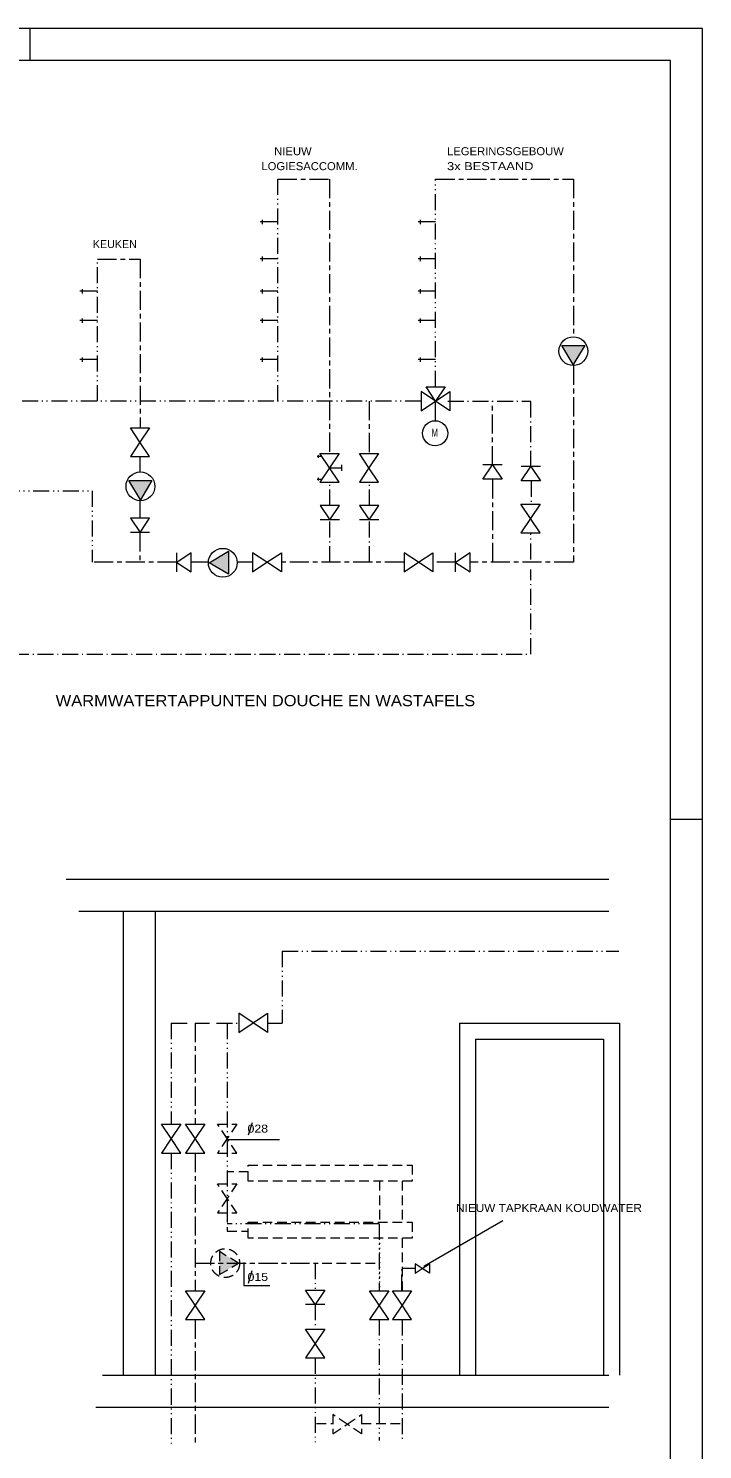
# Model space of a CAD drawing. Extents: x 295824 to 414724, y 24924 to 109024.
# Drawn here: x 393674 to 414724, y 64629 to 109024 of the extents above; entities that cross this region are included whole.
import ezdxf

# ---------------------------------------------------------------- set-up
doc = ezdxf.new("R2010")
doc.units = 0
doc.header["$LTSCALE"] = 100
for name, pattern in [('DASH_DOUBLE_DOT', [9.2, 5, -1.2, 0.3, -1.2, 0.3, -1.2]), ('DOT_DASHED', [7.7, 5, -1.2, 0.3, -1.2]), ('DOTTED', [1.5, 0.3, -1.2]), ('LONG_DASH_SHORT_DASH', [9.9, 6, -1.2, 1.5, -1.2]), ('MEDIUM_DASHED', [4.5, 3, -1.5])]:
    doc.linetypes.add(name, pattern=pattern)
for name, color, linetype, lineweight in [('1', 7, 'Continuous', 13), ('16', 7, 'Continuous', 13), ('30', 7, 'Continuous', 13)]:
    doc.layers.add(name, color=color, linetype=linetype, lineweight=lineweight)

msp = doc.modelspace()

# ---------------------------------------------------------------- hatches: boundary and pattern name
at = {"layer": '30'}
for points in [[(410326.8, 99122.5), (411046.8, 99122.5), (410686.8, 98522.5), (410686.8, 98522.5)], [(396810.4, 94898.8), (397530.4, 94898.8), (397170.4, 94298.8), (397170.4, 94298.8)], [(399922, 92692.6), (399922, 91972.6), (399322, 92332.6), (399322, 92332.6)], [(399637.9, 70813.8), (399637.9, 70093.8), (400237.9, 70453.8), (400237.9, 70453.8)]]:
    msp.add_hatch(color=256, dxfattribs=at).paths.add_polyline_path(points)

# ---------------------------------------------------------------- linework, layer by layer
at = {"layer": '1'}
for p, q in [((393723.6, 108023.8), (393723.6, 109023.8)), ((414723.6, 24923.8), (414723.6, 109023.8)), ((413723.6, 84323.8), (414723.6, 84323.8)), ((406017.2, 70354.9), (408491.4, 71783.4))]:
    msp.add_line(p, q, dxfattribs=at)
for points in [[(414723.6, 109023.8), (304995.6, 109023.8), (295823.6, 109023.8)], [(304995.6, 25923.8), (413723.6, 25923.8), (413723.6, 108023.8), (304995.6, 108023.8)]]:
    msp.add_lwpolyline(points, dxfattribs=at)
at = {"layer": '30', "linetype": 'DASH_DOUBLE_DOT'}
for p, q in [((401457.7, 97381.8), (401457.7, 104318.7)), ((406388, 97830.3), (406388, 104318.7)), ((395827.9, 97381.8), (395827.9, 101820.6)), ((405933, 97381.8), (391003.1, 97381.8)), ((391984.8, 94576.2), (395663, 94576.2)), ((395663, 94576.2), (395663, 92348.1)), ((401594.7, 80202), (412106, 80202)), ((401594.7, 80202), (401594.7, 77952)), ((398130.5, 77952), (398629.9, 77952)), ((398130.5, 77952), (398130.5, 74792)), ((398880.5, 77952), (399329.5, 77952)), ((399542.9, 77952), (400238.9, 77952)), ((399880.5, 77952), (399880.5, 71679.2)), ((401138.9, 77952), (401594.7, 77952)), ((398130.5, 73892), (398130.5, 64823.2)), ((404630.5, 71679.2), (399880.5, 71679.2)), ((404630.5, 71679.2), (404630.5, 69592.1)), ((402630.5, 70452), (402630.5, 69596.3)), ((402630.5, 69167), (402630.5, 68392.2)), ((404630.5, 68692.1), (404630.5, 64909)), ((402630.5, 67492.2), (402630.5, 64859.3))]:
    msp.add_line(p, q, dxfattribs=at)
at = {"layer": '30'}
for p, q in [((400977, 103044.6), (400977, 102905.8)), ((405907.2, 103044.6), (405907.2, 102905.8)), ((401457.7, 102977.9), (400910.4, 102977.9)), ((406388, 102977.9), (405840.6, 102977.9)), ((401457.7, 101827.9), (400910.4, 101827.9)), ((400977, 101894.6), (400977, 101755.8)), ((406388, 101827.9), (405840.6, 101827.9)), ((405907.2, 101894.6), (405907.2, 101755.8)), ((395827.9, 100811.3), (395280.5, 100811.3)), ((395347.2, 100877.9), (395347.2, 100739.2)), ((401457.7, 100811.3), (400910.4, 100811.3)), ((400977, 100877.9), (400977, 100739.2)), ((406388, 100811.3), (405840.6, 100811.3)), ((405907.2, 100877.9), (405907.2, 100739.2)), ((395827.9, 99894.6), (395280.5, 99894.6)), ((395347.2, 99961.3), (395347.2, 99822.5)), ((401457.7, 99894.6), (400910.4, 99894.6)), ((400977, 99961.3), (400977, 99822.5)), ((406388, 99894.6), (405840.6, 99894.6)), ((405907.2, 99961.3), (405907.2, 99822.5)), ((410686.8, 98522.5), (410326.8, 99122.5)), ((410326.8, 99122.5), (411046.8, 99122.5)), ((411046.8, 99122.5), (410686.8, 98522.5)), ((395827.9, 98678), (395280.5, 98678)), ((395347.2, 98744.6), (395347.2, 98605.9)), ((401457.7, 98678), (400910.4, 98678)), ((400977, 98744.6), (400977, 98605.9)), ((406388, 98678), (405840.6, 98678)), ((405907.2, 98744.6), (405907.2, 98605.9)), ((406376.9, 97387.4), (406376.9, 96754.1)), ((402832.6, 95652.3), (402685.6, 95652.3)), ((402718.9, 95693.9), (402718.9, 95610.6)), ((403068.7, 95293.9), (403451.8, 95293.9)), ((403451.8, 95393.9), (403451.8, 95202.3)), ((408464, 95388.2), (407864, 95388.2)), ((409663.2, 95338.2), (409063.2, 95338.2)), ((397170.4, 94298.8), (396810.4, 94898.8)), ((396810.4, 94898.8), (397530.4, 94898.8)), ((397530.4, 94898.8), (397170.4, 94298.8)), ((402834.7, 94935.6), (402685.6, 94935.6)), ((402718.9, 94985.6), (402718.9, 94902.3)), ((397458.6, 93279.7), (396858.6, 93279.7)), ((403383.8, 93670.1), (402783.8, 93670.1)), ((404616.4, 93670.1), (404016.4, 93670.1)), ((398302.9, 92044.4), (398302.9, 92644.4)), ((399322, 92332.6), (399922, 92692.6)), ((399922, 92692.6), (399922, 91972.6)), ((407014.1, 92044.4), (407014.1, 92644.4)), ((399922, 91972.6), (399322, 92332.6)), ((394850.1, 82452), (411793.9, 82452)), ((395249.9, 81452), (411793.9, 81452)), ((396630.5, 81452), (396630.5, 66952)), ((397630.5, 81452), (397630.5, 66952)), ((407130.5, 77952), (407130.5, 66952)), ((407130.5, 77952), (412130.5, 77952)), ((412130.5, 77952), (412130.5, 66952)), ((407630.5, 77452), (407630.5, 66952)), ((400663.2, 74837.5), (400529.9, 74454.2)), ((399913.6, 74312.5), (401512.7, 74312.5)), ((400646.5, 70212.6), (400539.8, 69814.4)), ((402325.1, 69175.5), (402925.1, 69175.5)), ((395982.7, 66952), (411793.9, 66952)), ((395782.9, 65952), (411793.9, 65952))]:
    msp.add_line(p, q, dxfattribs=at)
at = {"layer": '30', "linetype": 'LONG_DASH_SHORT_DASH'}
for p, q in [((410688.9, 98493.8), (410688.9, 92348.1)), ((404311.5, 97381.8), (404311.5, 95745.6)), ((408165.5, 95377.5), (408165.5, 97377.6)), ((397154.9, 95654), (397154.9, 95168.4)), ((408167.4, 94938.2), (408167.4, 92348.1)), ((397154.9, 94269.1), (397154.9, 93729.7)), ((397154.9, 93279.7), (397154.9, 92348.1)), ((398302.9, 92348.1), (395663, 92348.1)), ((399292.3, 92348.1), (398752.9, 92348.1)), ((400677.2, 92348.1), (400191.6, 92348.1)), ((405402.5, 92348.1), (401572.1, 92348.1)), ((407027.2, 92348.1), (406302.5, 92348.1)), ((410688.9, 92348.1), (407477.2, 92348.1)), ((398880.5, 77952), (398880.5, 74792)), ((398880.5, 73892), (398880.5, 69592.1)), ((398880.5, 70452), (402779.2, 70452)), ((398880.5, 68692.1), (398880.5, 64843.2))]:
    msp.add_line(p, q, dxfattribs=at)
at = {"layer": '30', "linetype": 'DOT_DASHED'}
for p, q in [((406766.1, 97377.6), (409364.8, 97377.6)), ((409364.8, 95327.5), (409364.8, 97377.6)), ((403087.2, 94120.1), (403087.2, 94840.8)), ((404319.8, 94120.1), (404319.8, 94840.8)), ((409366.7, 94888.2), (409366.7, 94167.5)), ((403087.2, 92348.1), (403087.2, 93670.1)), ((404319.8, 92348.1), (404319.8, 93670.1)), ((409364.8, 92435.6), (409364.8, 93248.3)), ((409364.8, 89477.3), (409364.8, 92119)), ((393187.2, 89477.3), (409364.8, 89477.3)), ((405340.9, 68692.1), (405340.9, 64929.3))]:
    msp.add_line(p, q, dxfattribs=at)
at = {"layer": '30', "linetype": 'MEDIUM_DASHED'}
for p, q in [((400538.8, 73301.3), (399877.9, 73301.3)), ((404631.7, 73018), (404631.7, 71734.7)), ((405342, 73018), (405342, 71734.7)), ((399877.9, 72025.4), (399877.9, 71451.3)), ((399877.9, 71451.3), (400505.5, 71451.3)), ((405342, 71234.7), (405342, 69592.1)), ((400237.9, 70453.8), (399637.9, 70813.8)), ((399637.9, 70813.8), (399637.9, 70093.8)), ((399637.9, 70093.8), (400237.9, 70453.8)), ((402845.8, 70452), (404611.4, 70452)), ((402670.8, 65443.1), (403178.4, 65443.1)), ((404078.4, 65443.1), (405342, 65443.1))]:
    msp.add_line(p, q, dxfattribs=at)
at = {"layer": '30', "linetype": 'DOTTED'}
msp.add_line((404631.7, 71234.7), (404631.7, 69592.1), dxfattribs=at)
at = {"layer": '30', "linetype": 'LONG_DASH_SHORT_DASH'}
for points in [[(401457.7, 104318.7), (403079, 104318.7), (403079, 95745.6)], [(406388, 104318.7), (410688.9, 104318.7), (410688.9, 99392.5)], [(395827.9, 101820.6), (397166, 101820.6), (397166, 96554.1)]]:
    msp.add_lwpolyline(points, dxfattribs=at)
at = {"layer": '30'}
for points in [[(410326.8, 99122.5), (411046.8, 99122.5), (410686.8, 98522.5), (410686.8, 98522.5)], [(405933, 97681.8), (405933, 97081.8), (406383, 97381.8)], [(406088, 97830.3), (406688, 97830.3), (406388, 97380.3)], [(406833, 97681.8), (406833, 97081.8), (406383, 97381.8)], [(396856, 96549), (397456, 96549), (397156, 96099)], [(396856, 95649), (397456, 95649), (397156, 96099)], [(402773.7, 95744.8), (403373.7, 95744.8), (403073.7, 95294.8)], [(404006.2, 95744.8), (404606.2, 95744.8), (404306.2, 95294.8)], [(402773.7, 94844.8), (403373.7, 94844.8), (403073.7, 95294.8)], [(404006.2, 94844.8), (404606.2, 94844.8), (404306.2, 95294.8)], [(408464, 94938.2), (407864, 94938.2), (408164, 95388.2)], [(409663.2, 94888.2), (409063.2, 94888.2), (409363.2, 95338.2)], [(396810.4, 94898.8), (397530.4, 94898.8), (397170.4, 94298.8), (397170.4, 94298.8)], [(403383.8, 94120.1), (402783.8, 94120.1), (403083.8, 93670.1)], [(404616.4, 94120.1), (404016.4, 94120.1), (404316.4, 93670.1)], [(409053.1, 94163.5), (409653.1, 94163.5), (409353.1, 93713.5)], [(397458.6, 93729.7), (396858.6, 93729.7), (397158.6, 93279.7)], [(409053.1, 93263.5), (409653.1, 93263.5), (409353.1, 93713.5)], [(398752.9, 92044.4), (398752.9, 92644.4), (398302.9, 92344.4)], [(399922, 92692.6), (399922, 91972.6), (399322, 92332.6), (399322, 92332.6)], [(400672.1, 92647), (400672.1, 92047), (401122.1, 92347)], [(401572.1, 92647), (401572.1, 92047), (401122.1, 92347)], [(405402.5, 92647), (405402.5, 92047), (405852.5, 92347)], [(406302.5, 92647), (406302.5, 92047), (405852.5, 92347)], [(407464.1, 92044.4), (407464.1, 92644.4), (407014.1, 92344.4)], [(400238.9, 78260.7), (400238.9, 77660.7), (400688.9, 77960.7)], [(401138.9, 78260.7), (401138.9, 77660.7), (400688.9, 77960.7)], [(397827.9, 74792), (398427.9, 74792), (398127.9, 74342)], [(398577.4, 74792), (399177.4, 74792), (398877.4, 74342)], [(397827.9, 73892), (398427.9, 73892), (398127.9, 74342)], [(398577.4, 73892), (399177.4, 73892), (398877.4, 74342)], [(405745.1, 70436.4), (405745.1, 70136.4), (405970.1, 70286.4)], [(406195.1, 70436.4), (406195.1, 70136.4), (405970.1, 70286.4)], [(398577.4, 69592.1), (399177.4, 69592.1), (398877.4, 69142.1)], [(402325.1, 69608.8), (402925.1, 69608.8), (402625.1, 69158.8)], [(404323.9, 69592.1), (404923.9, 69592.1), (404623.9, 69142.1)], [(405040.1, 69592.1), (405640.1, 69592.1), (405340.1, 69142.1)], [(398577.4, 68692.1), (399177.4, 68692.1), (398877.4, 69142.1)], [(404323.9, 68692.1), (404923.9, 68692.1), (404623.9, 69142.1)], [(405040.1, 68692.1), (405640.1, 68692.1), (405340.1, 69142.1)], [(402325.1, 68392.2), (402925.1, 68392.2), (402625.1, 67942.2)], [(402325.1, 67492.2), (402925.1, 67492.2), (402625.1, 67942.2)]]:
    msp.add_lwpolyline(points, close=True, dxfattribs=at)
for points in [[(407630.5, 77452), (411630.5, 77452), (411630.5, 66952)], [(400396.7, 70470.9), (400396.7, 69754.3), (401212.8, 69754.3)]]:
    msp.add_lwpolyline(points, dxfattribs=at)
at = {"layer": '30', "linetype": 'MEDIUM_DASHED'}
for points in [[(399577.9, 74792), (400177.9, 74792), (399877.9, 74342)], [(399577.9, 73892), (400177.9, 73892), (399877.9, 74342)], [(400538.8, 73518), (405652.3, 73518), (405652.3, 73018), (400538.8, 73018)], [(399577.9, 72925.4), (400177.9, 72925.4), (399877.9, 72475.4)], [(399577.9, 72025.4), (400177.9, 72025.4), (399877.9, 72475.4)], [(400538.8, 71734.7), (405652.3, 71734.7), (405652.3, 71234.7), (400538.8, 71234.7)], [(399637.9, 70813.8), (399637.9, 70093.8), (400237.9, 70453.8), (400237.9, 70453.8)], [(403178.4, 65724.7), (403178.4, 65124.7), (403628.4, 65424.7)], [(404078.4, 65724.7), (404078.4, 65124.7), (403628.4, 65424.7)]]:
    msp.add_lwpolyline(points, close=True, dxfattribs=at)
at = {"layer": '30', "linetype": 'DOT_DASHED'}
msp.add_lwpolyline([(405338.3, 69599.5), (405338.3, 70291.2), (405746.4, 70291.2)], dxfattribs=at)
at = {"layer": '30'}
for centre, radius in [((410686.8, 98942.5), 450), ((406372.9, 96376.9), 392.1), ((397170.4, 94718.8), 450), ((399741.9, 92332.6), 450)]:
    msp.add_circle(centre, radius, dxfattribs=at)
at = {"layer": '30', "linetype": 'MEDIUM_DASHED'}
msp.add_circle((399817.9, 70453.8), 450, dxfattribs=at)

# ---------------------------------------------------------------- texts
at = {"layer": '16'}
for s, width, p in [('028', 1.15, (400514.6, 74530.2)), ('NIEUW TAPKRAAN KOUDWATER', 1.1, (407027.6, 72051.7)), ('015', 1.15, (400514.6, 69896.9))]:
    msp.add_text(s, height=250, dxfattribs=dict(at, width=width)).set_placement(p)
at = {"layer": '30'}
for s, height, width, p in [('NIEUW', 250, 1.05, (401348.1, 105062.6)), ('LEGERINGSGEBOUW', 250, 1.05, (406744.8, 105062.6)), ('LOGIESACCOMM.', 250, 1.05, (400948.4, 104596)), ('3x BESTAAND', 250, 1.2, (406744.8, 104596)), ('M', 250, 0.7, (406263.5, 96268.5)), ('WARMWATERTAPPUNTEN DOUCHE EN WASTAFELS', 350, 1.1, (394523.5, 87851.1))]:
    msp.add_text(s, height=height, dxfattribs=dict(at, width=width)).set_placement(p)
msp.add_text('KEUKEN', height=250, dxfattribs=at).set_placement((395685, 102162.7))

doc.saveas('drawing.dxf')
